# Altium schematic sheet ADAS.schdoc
size 839 x 594 mm; Symbol: Drawing-Symbol_A4; Company: 嘉立创EDA; Version: V1.0; Page Size: A4; @Project Name: mairui N1; @Update Date: 2026-05-07; @Create Date: 2026-05-07; Device: Drawing-Symbol_A4; @Board Name: 顶板; @Page Name: P1; @Create Time: 15:28:40; @Page Count: 5; @Page No: 5; @Schematic Name: #第七届立创电赛#卡片型多参数监护仪-OpenECG_6; @Update Time: 15:28:40; @Assembly Variant: Basic; Border: 1; Title Block Position: 3; Size: A4; Width: 3304; Height: 2338; Region Start: 1; X Region Count: 6; Y Region Count: 4; Blade Width: 10
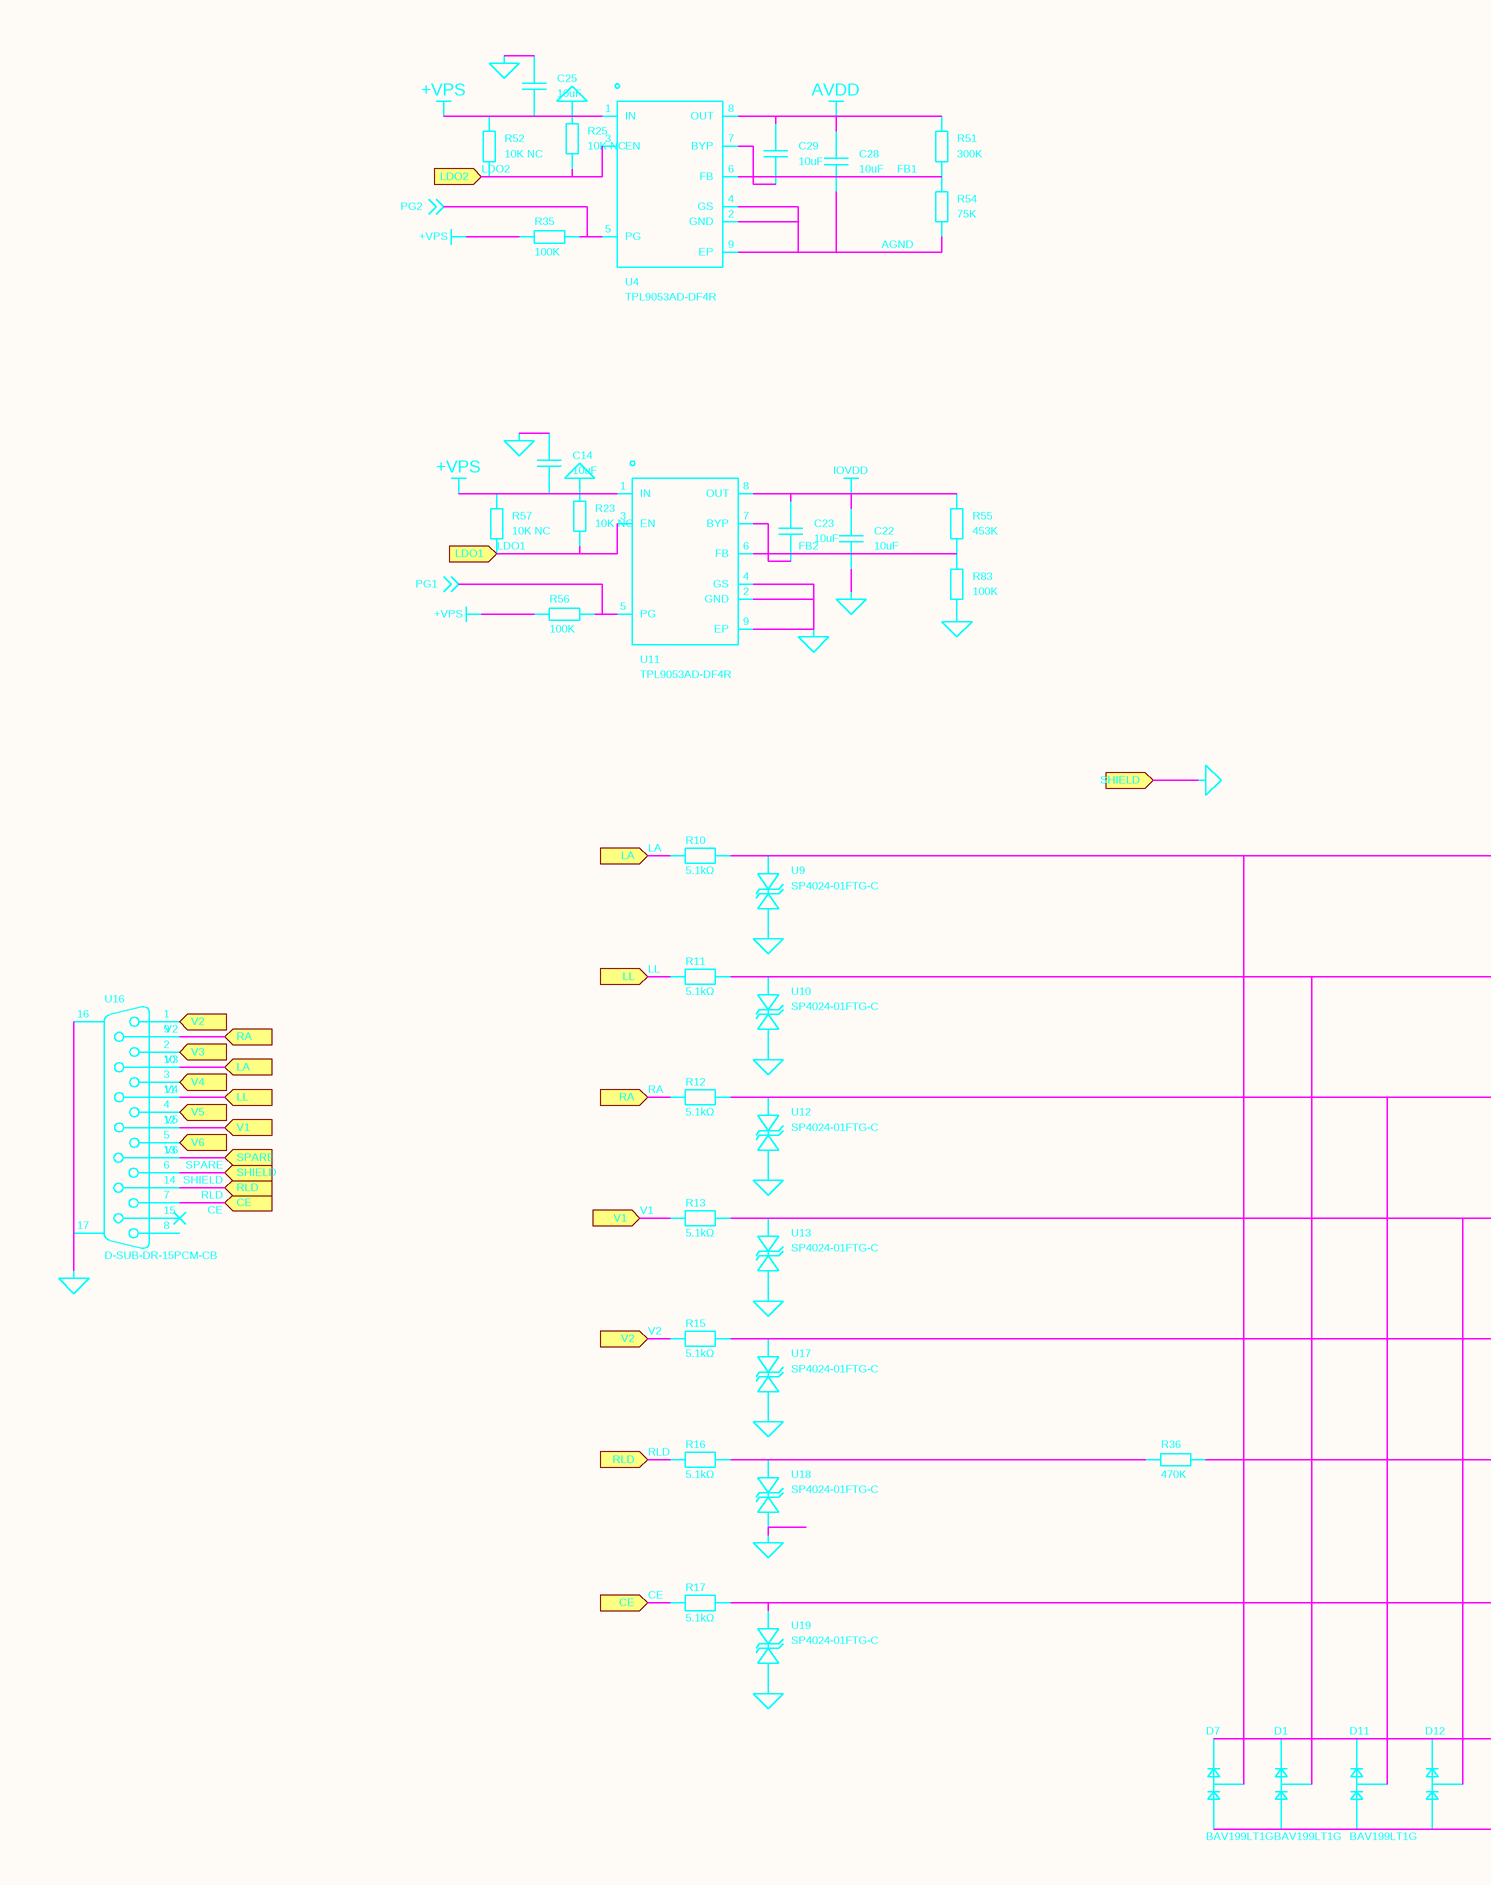
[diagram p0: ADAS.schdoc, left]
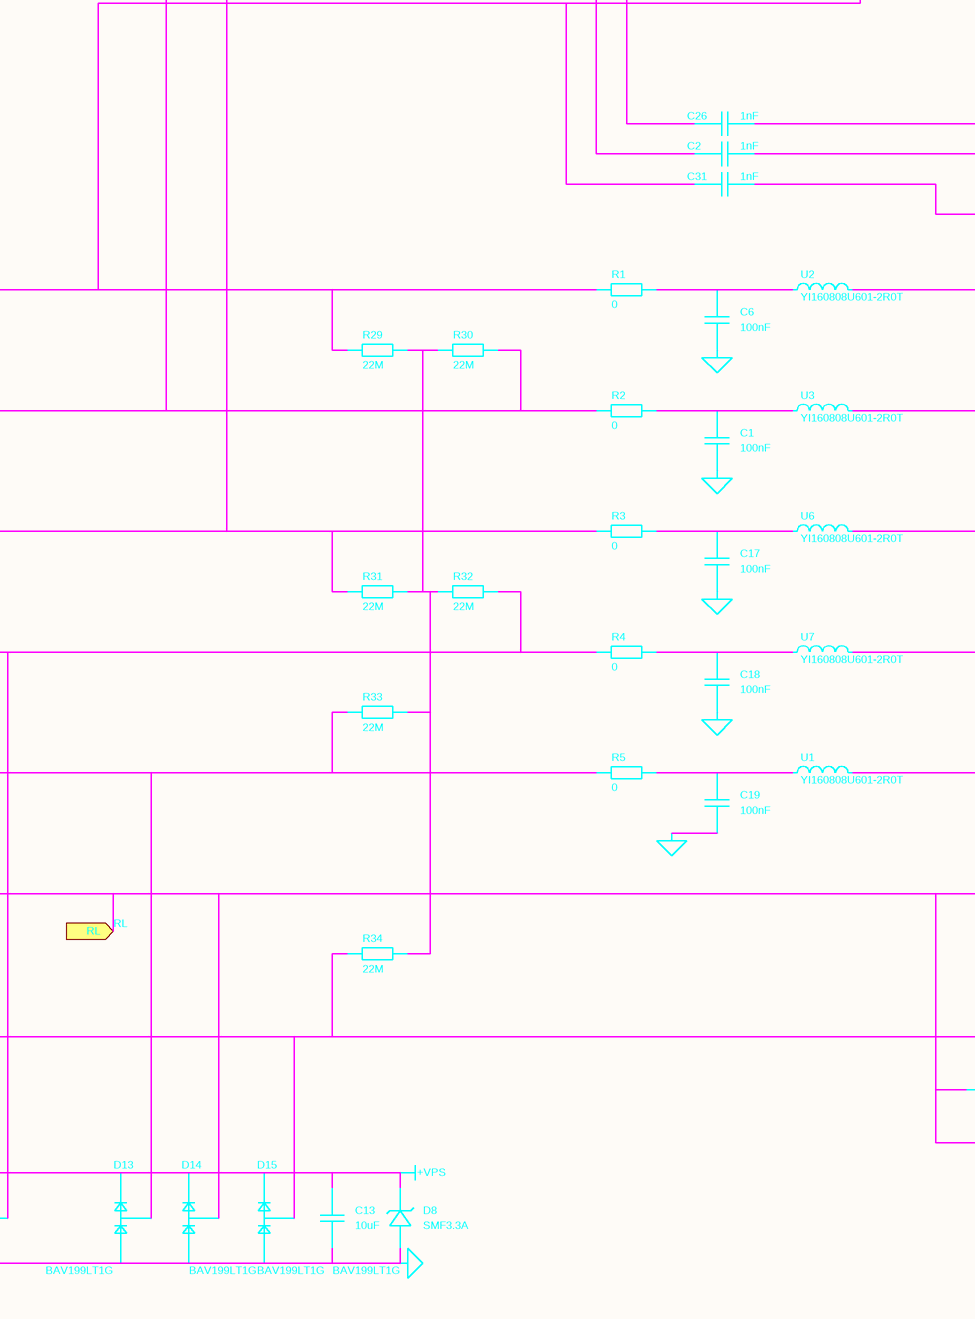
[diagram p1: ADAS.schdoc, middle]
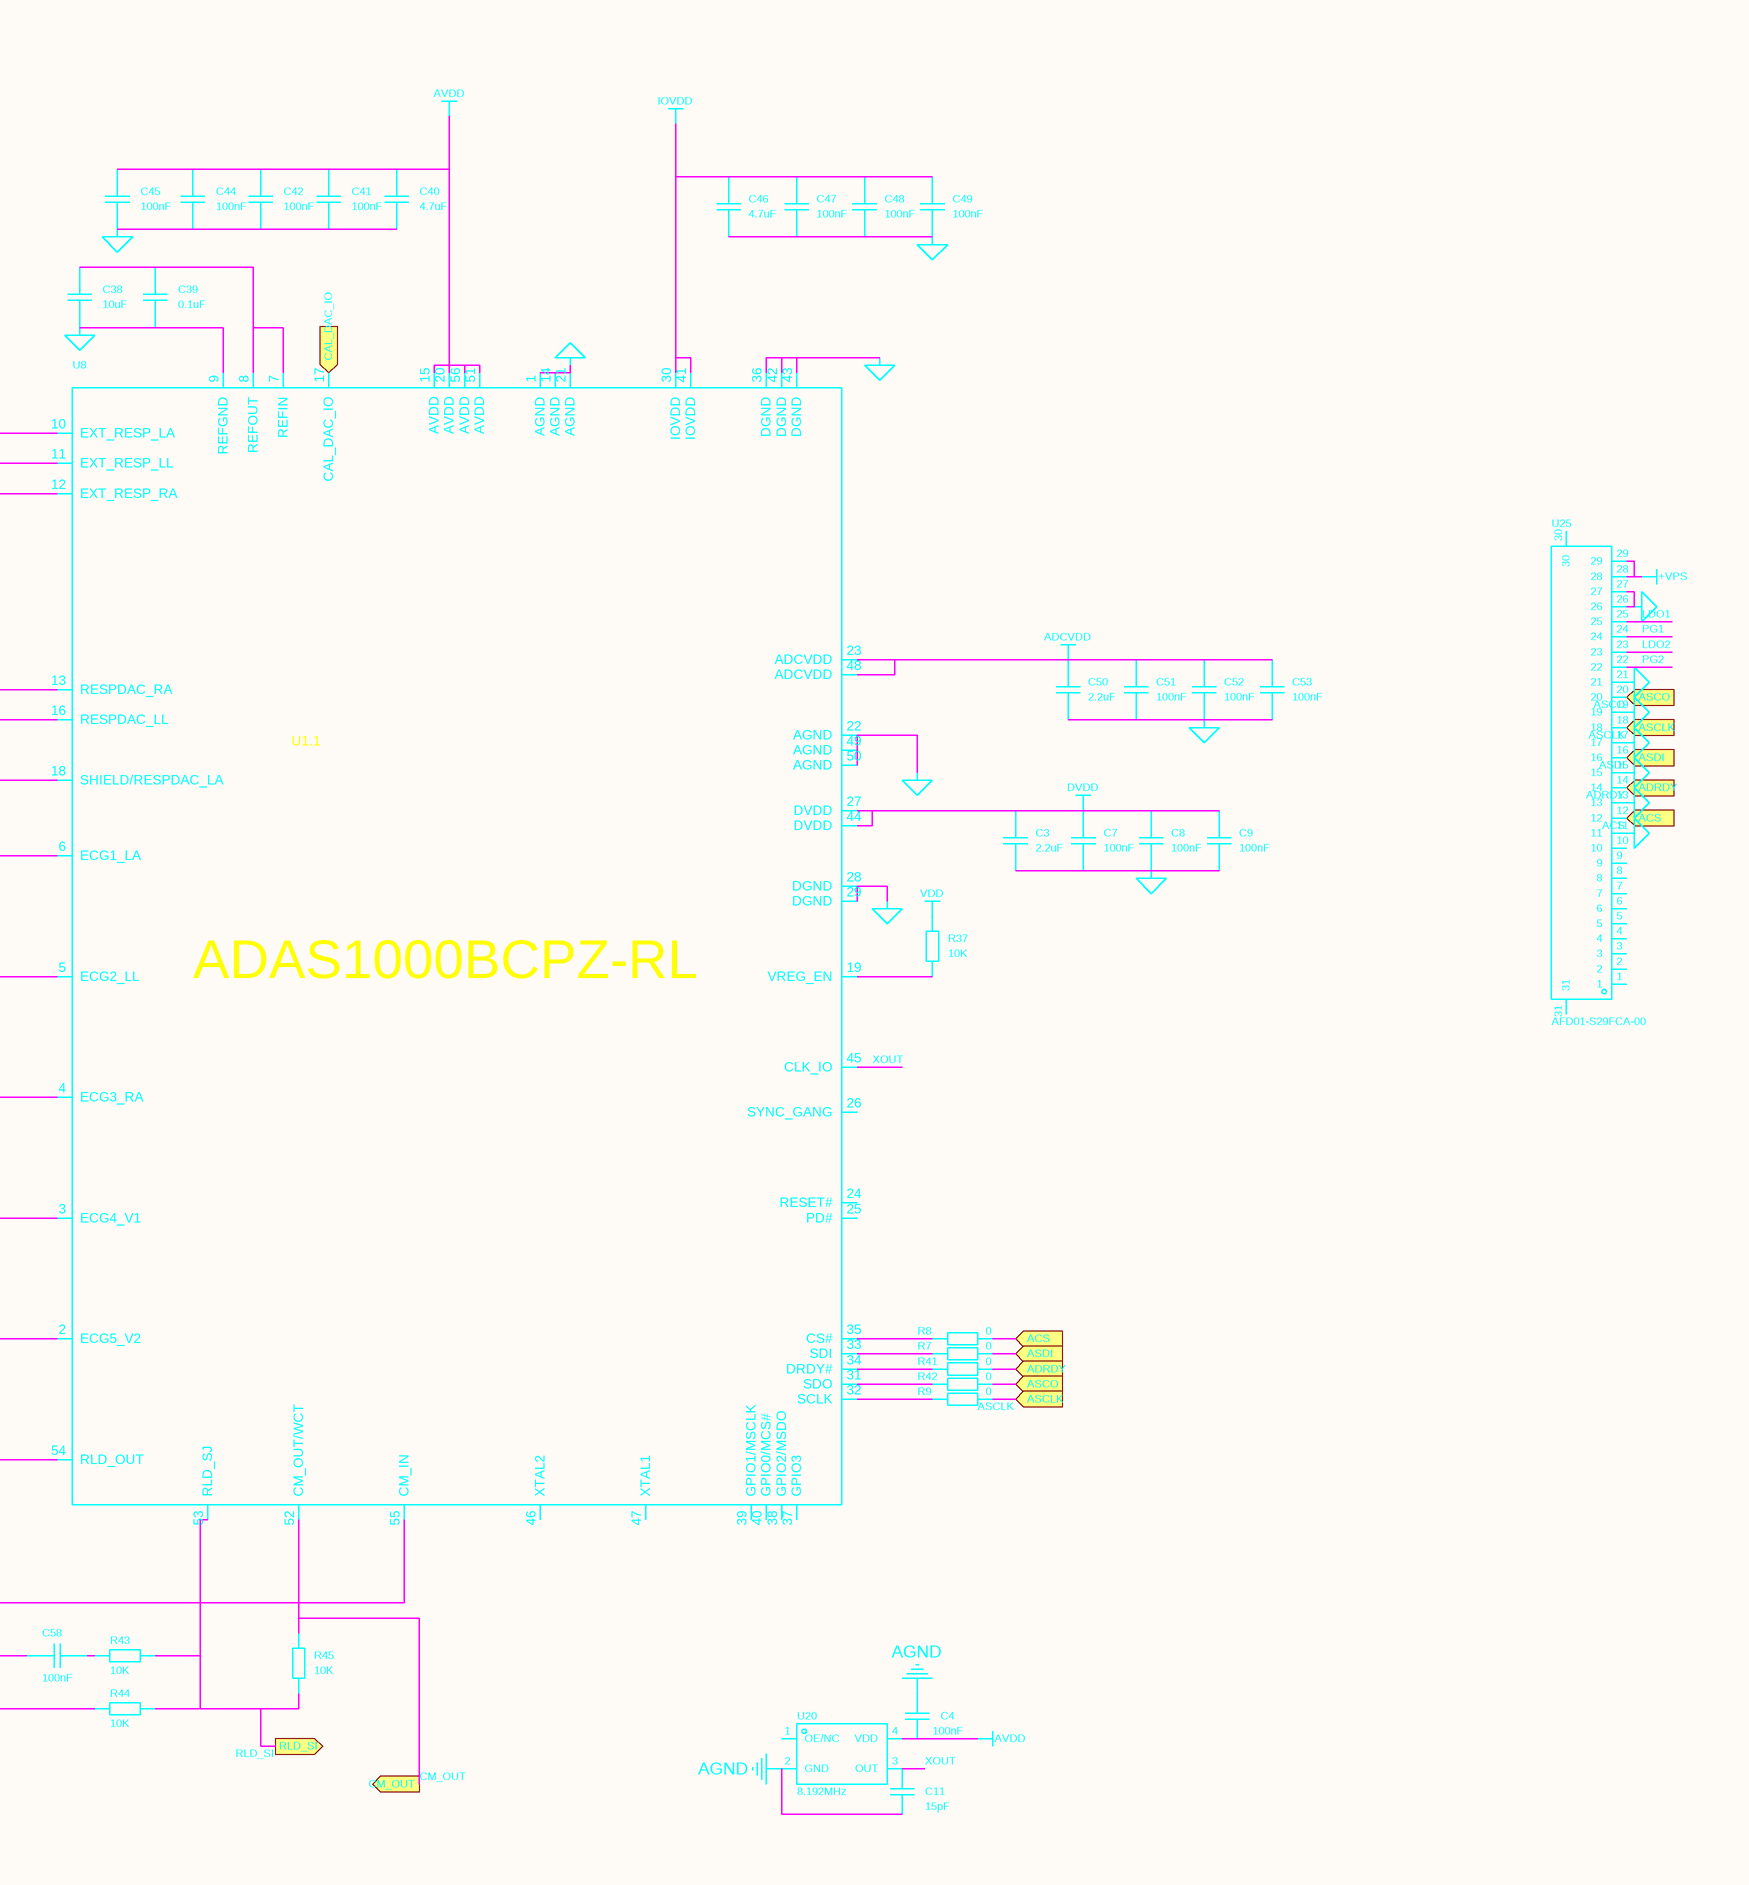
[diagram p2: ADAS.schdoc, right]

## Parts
C1  100nF  [C0603]
C2  1nF  [C0603]
C3  2.2uF  [C0603]
C4  100nF  [C0603]
C6  100nF  [C0603]
C7  100nF  [C0603]
C8  100nF  [C0603]
C9  100nF  [C0603]
C11  15pF  [C0603]
C13  10uF  [C0603]
C14  10uF  [C0603]
C17  100nF  [C0603]
C18  100nF  [C0603]
C19  100nF  [C0603]
C22  10uF  [C0805]
C23  10uF  [C0603]
C25  10uF  [C0603]
C26  1nF  [C0603]
C28  10uF  [C0603]
C29  10uF  [C0603]
C31  1nF  [C0603]
C38  10uF  [C0603]
C39  0.1uF  [C0603]
C40  4.7uF  [C0603]
C41  100nF  [C0603]
C42  100nF  [C0603]
C44  100nF  [C0603]
C45  100nF  [C0603]
C46  4.7uF  [C0603]
C47  100nF  [C0603]
C48  100nF  [C0603]
C49  100nF  [C0603]
C50  2.2uF  [C0603]
C51  100nF  [C0603]
C52  100nF  [C0603]
C53  100nF  [C0603]
C58  100nF  [C0603]
D1  BAV199LT1G  [SOT-23_L2.9-W1.3-P1.90-LS2.4-BR]
D7  BAV199LT1G  [SOT-23_L2.9-W1.3-P1.90-LS2.4-BR]
D8  SMF3.3A  [SOD-123FL_L2.7-W1.8-LS3.7-RD]
D11  BAV199LT1G  [SOT-23_L2.9-W1.3-P1.90-LS2.4-BR]
D12  BAV199LT1G  [SOT-23_L2.9-W1.3-P1.90-LS2.4-BR]
D13  BAV199LT1G  [SOT-23_L2.9-W1.3-P1.90-LS2.4-BR]
D14  BAV199LT1G  [SOT-23_L2.9-W1.3-P1.90-LS2.4-BR]
D15  BAV199LT1G  [SOT-23_L2.9-W1.3-P1.90-LS2.4-BR]
R1  0  [R0603]
R2  0  [R0603]
R3  0  [R0603]
R4  0  [R0603]
R5  0  [R0603]
R7  0  [R0603]
R8  0  [R0603]
R9  0  [R0603]
R10  5.1kΩ  [R0207]
R11  5.1kΩ  [R0207]
R12  5.1kΩ  [R0207]
R13  5.1kΩ  [R0207]
R15  5.1kΩ  [R0207]
R16  5.1kΩ  [R0207]
R17  5.1kΩ  [R0207]
R23  10K NC  [R0603]
R25  10K NC  [R0603]
R29  22M  [R0603]
R30  22M  [R0603]
R31  22M  [R0603]
R32  22M  [R0603]
R33  22M  [R0603]
R34  22M  [R0603]
R35  100K  [R0603]
R36  470K  [R0603]
R37  10K  [R0603]
R41  0  [R0603]
R42  0  [R0603]
R43  10K  [R0603]
R44  10K  [R0603]
R45  10K  [R0603]
R51  300K  [R0603]
R52  10K NC  [R0603]
R54  75K  [R0603]
R55  453K  [R0603]
R56  100K  [R0603]
R57  10K NC  [R0603]
R83  100K  [R0603]
U1  YI160808U601-2R0T  [L0603]
U2  YI160808U601-2R0T  [L0603]
U3  YI160808U601-2R0T  [L0603]
U4  TPL9053AD-DF4R  [TDFN-8_L2.0-W2.0-P0.50-BL-EP1.2-1]
U6  YI160808U601-2R0T  [L0603]
U7  YI160808U601-2R0T  [L0603]
U8  (no value)  [LFCSP-56_L9.0-W9.0-P0.40-BL]
U9  SP4024-01FTG-C  [SOD-323_L1.8-W1.3-LS2.5-BI]
U10  SP4024-01FTG-C  [SOD-323_L1.8-W1.3-LS2.5-BI]
U11  TPL9053AD-DF4R  [TDFN-8_L2.0-W2.0-P0.50-BL-EP1.2-1]
U12  SP4024-01FTG-C  [SOD-323_L1.8-W1.3-LS2.5-BI]
U13  SP4024-01FTG-C  [SOD-323_L1.8-W1.3-LS2.5-BI]
U16  D-SUB-DR-15PCM-CB  [DSUB-TH_XUNPU_D-SUB-DR-15PCM-CB]
U17  SP4024-01FTG-C  [SOD-323_L1.8-W1.3-LS2.5-BI]
U18  SP4024-01FTG-C  [SOD-323_L1.8-W1.3-LS2.5-BI]
U19  SP4024-01FTG-C  [SOD-323_L1.8-W1.3-LS2.5-BI]
U20  8.192MHz  [OSC-SMD_4P-L2.5-W2.0-BL]
U25  AFD01-S29FCA-00  [FPC-SMD_29P-P0.50_JS_AFD01-S29FCA-00]

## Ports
ACS (in), ADRDY (in), ASCLK (in), ASCO (in), ASDI (in), CAL_DAC_IO (in), CE (in), CM_OUT (out), LA (in), LDO1 (in), LDO2 (in), LL (in), RA (in), RL (in), RLD (in), RLD_SI (out), SHIELD (in), SPARE (in), V1 (in), V2 (in), V3 (in), V4 (in), V5 (in), V6 (in)

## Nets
+VPS: C13.1 C14.1 C25.1 D1.2(C) D7.2(C) D8.1(C) D11.2(C) D12.2(C) D13.2(C) D14.2(C) D15.2(C) R35.1 R52.2 R56.1 R57.2 U4.1(IN) U11.1(IN) U25.28 U25.29
ADCVDD: C50.2 C51.2 C52.2 C53.2 U8.23(ADCVDD) U8.48(ADCVDD)
AGND: C1.1 C3.1 C4.1 C6.1 C7.1 C8.1 C9.1 C11.2 C13.2 C14.2 C17.1 C18.1 C19.1 C22.1 C25.2 C28.1 C38.1 C39.1 C40.1 C41.1 C42.1 C44.1 C45.1 C46.1 C47.1 C48.1 C49.1 C50.1 C51.1 C52.1 C53.1 D1.1(A) D7.1(A) D8.2(A) D11.1(A) D12.1(A) D13.1(A) D14.1(A) D15.1(A) R23.2 R25.2 R54.1 R83.1 U4.2(GND) U4.4(GS) U4.9(EP) U8.1(AGND) U8.9(REFGND) U8.14(AGND) U8.21(AGND) U8.22(AGND) U8.28(DGND) U8.29(DGND) U8.36(DGND) U8.42(DGND) U8.43(DGND) U8.49(AGND) U8.50(AGND) U9.1(IO) U10.1(IO) U11.2(GND) U11.4(GS) U11.9(EP) U12.1(IO) U13.1(IO) U16.6 U16.16(MH2) U16.17(MH1) U17.1(IO) U18.1(IO) U19.1(IO) U20.2(GND) U25.11 U25.13 U25.15 U25.17 U25.19 U25.21 U25.26 U25.27 ; port SHIELD  [also labelled SHIELD]
AVDD: C4.2 C28.2 C29.2 C40.2 C41.2 C42.2 C44.2 C45.2 R51.2 U4.8(OUT) U8.15(AVDD) U8.20(AVDD) U8.51(AVDD) U8.56(AVDD) U20.4(VDD)
DVDD: C3.2 C7.2 C8.2 C9.2 U8.27(DVDD) U8.44(DVDD)
IOVDD: C22.2 C23.2 C46.2 C47.2 C48.2 C49.2 R55.2 U8.30(IOVDD) U8.41(IOVDD) U11.8(OUT)
VDD: R37.2
ACS: R8.1 U25.12 ; port ACS
ADRDY: R41.1 U25.14 ; port ADRDY
ASCLK: R9.1 U25.18 ; port ASCLK
ASCO: R42.1 U25.20 ; port ASCO
ASDI: R7.1 U25.16 ; port ASDI
CAL_DAC_IO: U8.17(CAL_DAC_IO) ; port CAL_DAC_IO
CE: R17.1 U16.7 ; port CE
CM_OUT: R45.2 U8.52(CM_OUT/WCT) ; port CM_OUT
FB1: R51.1 R54.2 U4.6(FB)
FB2: R55.1 R83.2 U11.6(FB)
LA: R10.1 U16.10 ; port LA
LDO1: R23.1 R57.1 U11.3(EN) U25.25 ; port LDO1
LDO2: R25.1 R52.1 U4.3(EN) U25.23 ; port LDO2
LL: R11.1 U16.11 ; port LL
PG1: R56.2 U11.5(PG) U25.24 ; off-sheet PG1
PG2: R35.2 U4.5(PG) U25.22 ; off-sheet PG2
RA: R12.1 U16.9 ; port RA
RL: C58.1 D14.3(C/A) R36.2 R44.1 U8.54(RLD_OUT) ; port RL
RLD: R16.1 U16.14 ; port RLD
RLD_SI: R43.2 R44.2 R45.1 U8.53(RLD_SJ) ; port RLD_SI
SPARE: U16.13 ; port SPARE
V1: R13.1 U16.12 ; port V1
V2: R15.1 U16.1 ; port V2
V3: U16.2 ; port V3
V4: U16.3 ; port V4
V5: U16.4 ; port V5
V6: U16.5 ; port V6
XOUT: C11.1 U8.45(CLK_IO) U20.3(OUT)
NetC1_2: C1.2 R2.2 U3.1
NetC2_1: C2.1 D1.3(C/A) R2.1 R11.2 R30.2 U8.11(EXT_RESP_LL) U10.2(IO)
NetC2_2: C2.2 U8.16(RESPDAC_LL)
NetC6_2: C6.2 R1.2 U2.1
NetC17_2: C17.2 R3.2 U6.1
NetC18_2: C18.2 R4.2 U7.1
NetC19_2: C19.2 R5.2 U1.1
NetC23_1: C23.1 U11.7(BYP)
NetC26_1: C26.1 D11.3(C/A) R3.1 R12.2 R31.1 U8.10(EXT_RESP_LA) U12.2(IO)
NetC26_2: C26.2 U8.13(RESPDAC_RA)
NetC29_1: C29.1 U4.7(BYP)
NetC31_1: C31.1 D7.3(C/A) R1.1 R10.2 R29.1 U8.12(EXT_RESP_RA) U9.2(IO)
NetC31_2: C31.2 U8.18(SHIELD/RESPDAC_LA)
NetC38_2: C38.2 C39.2 U8.7(REFIN) U8.8(REFOUT)
NetC58_2: C58.2 R43.1
NetD12_3: D12.3(C/A) R4.1 R13.2 R32.2 U13.2(IO)
NetD13_3: D13.3(C/A) R5.1 R15.2 R29.2 R30.1 R31.2 R32.1 R33.1 R33.2 R34.2 U17.2(IO)
NetD15_3: D15.3(C/A) R17.2 R34.1 U8.55(CM_IN) U19.2(IO)
NetR7_2: R7.2 U8.33(SDI)
NetR8_2: R8.2 U8.35(CS#)
NetR9_2: R9.2 U8.32(SCLK)
NetR16_2: R16.2 R36.1 U18.2(IO)
NetR37_1: R37.1 U8.19(VREG_EN)
NetR41_2: R41.2 U8.34(DRDY#)
NetR42_2: R42.2 U8.31(SDO)
NetU1_2: U1.2 U8.2(ECG5_V2)
NetU2_2: U2.2 U8.6(ECG1_LA)
NetU3_2: U3.2 U8.5(ECG2_LL)
NetU6_2: U6.2 U8.4(ECG3_RA)
NetU7_2: U7.2 U8.3(ECG4_V1)

Not connected (* = marked no-connect by the designer): U8 24(RESET#) 25(PD#) 26(SYNC_GANG) 37(GPIO3) 38(GPIO2/MSDO) 39(GPIO1/MSCLK) 40(GPIO0/MCS#) 46(XTAL2) 47(XTAL1); U16 8 15*; U20 1(OE/NC); U25 1 2 3 4 5 6 7 8 9 10 30 31

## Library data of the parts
C1-C3 C6-C9 C14 C17-C19 C25 C26 C31 C38-C42 C44-C53 C58 = CAP_0603: Symbol: Capacitance; 3D Model: ac125912035d415993ca9572d50418b1; 3D Model Transform: 62.992,31.496,0,0,0,0,0,0,0; ConvertToPcb: yes; ModelName: C0603_L1.6-W0.8-H0.8
C4 C11 = CL10C200JB8NNNC: 容值:20pF;精度:±5%;额定电压:50V;温度系数:C0G;; Manufacturer: SAMSUNG(三星); Temperature Coefficient: C0G; 3D Model: ac125912035d415993ca9572d50418b10819f05c4eef4c71ace90d822a990e87; 3D Model Transform: 62.992,31.496,0,0,0,0,0,0,0; Tolerance: ±5%; Voltage Rating: 50V; AddInBom: yes; ModelName: C0603_L1.6-W0.8-H0.8
C13 = CL10A106KP8NNNC: 容值:10uF;精度:±10%;额定电压:10V;材质(温度系数):X5R;; Manufacturer: SAMSUNG(三星); 3D Model: ac125912035d415993ca9572d50418b1; 3D Model Transform: 62.992,31.496,0,0,0,0,0,0,0; Tolerance: ±10%; Voltage Rated: 10V; Temperature Coefficient: X5R; AddInBom: yes; ModelName: C0603_L1.6-W0.8-H0.8
C22 C23 C28 C29 = CGA0603X7R104K500JT: 容值:100nF;精度:±10%;额定电压:50V;温度系数:X7R;; Manufacturer: HRE(芯声); 3D Model: ac125912035d415993ca9572d50418b10819f05c4eef4c71ace90d822a990e87; 3D Model Transform: 62.992,31.496,0,0,0,0,0,0,0; Tolerance: ±10%; Voltage Rating: 50V; Temperature Coefficient: X7R; AddInBom: yes; ModelName: C0603_L1.6-W0.8-H0.8
D1 D7 D11-D15 = BAV199LT1G: 二极管配置:1对串联式;正向压降(Vf):1.25V@150mA;直流反向耐压(Vr):70V;整流电流:215mA;; Manufacturer: onsemi(安森美); 3D Model: c62791f0466c4ae2a892c056b845b0ca0819f05c4eef4c71ace90d822a990e87; 3D Model Transform: 98.64468,114.173,0,180,0,0,0.001,-0.002,0; Diode Configuration: 1对串联式; Voltage - DC Reverse(Vr): 70V; Current - Rectified: 215mA; Reverse Leakage Current (Ir): 5uA@70V; Non-Repetitive Peak Forward Surge Current: 2A; Operating Junction Temperature Range: -65℃~+150℃; AddInBom: yes; ModelName: SOT-23-3P_L2.9-W1.3-H1.0-LS2.4-P0.95
D8 = SMF3.3A_C51891832: 极性:单向;反向截止电压(Vrwm):3.3V;钳位电压:8.8V;峰值脉冲电流(Ipp):22.7A@10/1000us;峰值脉冲功率(Ppp):200W@10/1000us;击穿电压:6.5V;; Manufacturer: R+O(宏嘉诚); 3D Model: 86f9151e155e4fe2af0c4f2e0a80302e0819f05c4eef4c71ace90d822a990e87; 3D Model Transform: 141.732,70.866,0,180,0,0,0,0,0; Polarity: 单向; Reverse Stand-Off Voltage (Vrwm): 3.3V; Clamping Voltage: 8.8V; Voltage - Breakdown: 6.5V; Reverse Leakage Current (Ir): 500uA; Number of Channels: 单路; level of protection: IEC 61000-4-2; Type: TVS; AddInBom: yes; ModelName: SOD-123FL_L2.8-W1.8-H1.1-LS3.6
R1-R5 R7-R9 R23 R25 R29-R37 R41-R45 R51 R52 R55-R57 R83 = Res_0603: Symbol: 电阻; 3D Model: fc143cca1e79419f9cd78b61e9279f08; 3D Model Transform: 31.8897,63.7794,0,90,0,0,0,0,0; ConvertToPcb: yes
R10-R13 R15-R17 = MMB02070C5101FB200: 电阻类型:薄膜电阻;阻值:5.1kΩ;精度:±1%;功率:1W;工作电压:350V;温度系数:±50ppm/℃;; Manufacturer: VISHAY(威世); AddInBom: yes; ModelId: 8a8d73fdb19d414494ee443432156abe0819f05c4eef4c71ace90d822a990e87; ModelTransform: 228.346,86.3718,0,0,0,0,0,0,0; Tolerance: ±1%; Power(Watts): 1W; Voltage-Supply(Max): 350V
R54 = Res_0603: Symbol: 电阻_1; 3D Model: fc143cca1e79419f9cd78b61e9279f08; 3D Model Transform: 31.8897,63.7794,0,90,0,0,0,0,0; ConvertToPcb: yes
U1-U3 U6 U7 = YI160808U601-2R0T: 阻抗@频率:600Ω@100MHz;误差:±25%;直流电阻(DCR):100mΩ;; Manufacturer: YJYCOIN(益嘉源); AddInBom: yes; ModelId: 2bc5ec593d464d6ba9807aec0b5673c20819f05c4eef4c71ace90d822a990e87; ModelName: L0603_L1.6-W0.8-H0.5_BEAD; ModelTransform: 62.992,31.496,0,180,0,0,0.094,0.629,0; Tolerance: ±25%; DC Resistance(DCR): 100mΩ; Current Rating: 2A; Number of Circuits: 1
U4 U11 = TPL9053AD-DF4R: 输出类型:可调;工作电压:5.5V;输出电压:600mV~5.3V;输出电流:500mA;电源纹波抑制比(PSRR):89dB@(1kHz);输出极性:正极;; Manufacturer: 3PEAK(思瑞浦); 3D Model: b49c8915bf294a749a4f3b0eafd555820819f05c4eef4c71ace90d822a990e87; 3D Model Transform: 79.527,79.1337,0,0,0,0,0,0,0; Output Type: 可调; Voltage - Supply: 5.5V; Output Current: 500mA; Voltage Dropout: 150mV@(500mA); standby current: 130uA; Noise: 5.7uVrms; Output Configuration: 正极; AddInBom: yes
U8 = ADAS1000: AddInBom: yes
U9 U10 U12 U13 U17-U19 = SP4024-01FTG-C_C39832193: 极性:双向;反向截止电压(Vrwm):24V;最大钳位电压:42V;峰值脉冲电流(Ipp):8A;峰值脉冲功率(Ppp):350W;; Manufacturer: ElecSuper(静芯微); AddInBom: yes; ModelId: f9eb3c564310447fa7e5a2d35bef37870819f05c4eef4c71ace90d822a990e87; ModelTransform: 98.425,51.181,0,0,0,0,0,0,0; polarity: 双向; Reverse Stand-Off Voltage (Vrwm): 24V; Maximum Clamping Voltage: 42V; Peak Pulse Current (Ipp): 8A; Peak Pulse Power Dissipation (Ppp): 350W; Reverse Leakage Current (Ir): 100nA; Number of Lines: 单路
U16 = D-SUB-DR-15PCM-CB: 公母:母;总PIN位数:15P;安装方式:弯插;排数:2;额定电流-信号脚:3A;工作温度:-40℃~+105℃;; Manufacturer: XUNPU(讯普); 3D Model: 4ef65f5af92d43e696412c3cec25d44c0819f05c4eef4c71ace90d822a990e87; 3D Model Transform: 1543.304,720.86474,0,0,0,0,0,-246.062,-137.795; Gender: 母; Current Rating-Signal: 3A; AddInBom: yes
U20 = SX2M8.192M20F30TNN: 频率:8.192MHz;常温频差:±20ppm;输出模式:CMOS;工作电压:1.62V~3.63V;工作电流:10mA;频率稳定度:±30ppm;; Manufacturer: SCTF(星通时频); AddInBom: yes; ModelId: 6c59bf18646c482ead3932fe5df364850819f05c4eef4c71ace90d822a990e87; ModelName: OSC-SMD_4P-L2.5-W2.0-H0.6; ModelTransform: 98.425,78.74,0,0,0,0,0.0005,0,0; Normal temperature Frequency Tolerance: ±20ppm; Output Type: CMOS; Current - Supply: 10mA; Frequency Stability: ±30ppm
U25 = AFD01-S29FCA-00: 锁定特性:翻盖式;触点类型:下接;触点数量:29P;间距:0.5mm;安装方式:卧贴;; Manufacturer: JS(钜硕电子); AddInBom: yes; ModelId: d3d70d81697947e89ddc2db5d0f11f510819f05c4eef4c71ace90d822a990e87; ModelTransform: 783.463,240.157,0,0,0,0,-0.002,71.104,0; Locking Feature: 翻盖式; Number of Contacts: 29P; Pitch: 0.5mm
